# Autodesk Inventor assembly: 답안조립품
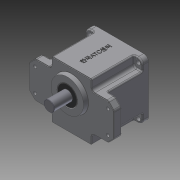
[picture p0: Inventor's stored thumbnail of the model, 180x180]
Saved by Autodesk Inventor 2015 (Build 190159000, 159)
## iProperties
Created: 2016-02
Part Number: 답안조립품
Document SubType Name: Assembly
Designer: Administrator
Author: Administrator
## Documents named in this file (10)
- C:\Users\Administrator\Desktop\460209V1019\답안조립품.iam
- C:\Users\Administrator\Desktop\460209V1019\본체.ipt
- C:\Users\Administrator\Desktop\460209V1019\커버.ipt
- C:\Users\Administrator\Desktop\460209V1019\볼트 M4 x 10.ipt
- C:\Users\Administrator\Desktop\460209V1019\오일실 8 22 7.ipt
- C:\Users\Administrator\Desktop\460209V1019\베어링 608.ipt
- C:\Users\Administrator\Desktop\460209V1019\메인축.ipt
- C:\Users\Administrator\Desktop\460209V1019\오일실 17 32 8.ipt
- C:\Users\Administrator\Desktop\460209V1019\베어링 6003.ipt
- C:\Users\Administrator\Desktop\460209V1019\서브축.ipt
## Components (2 placed, 1 different names)
1. ISO 4762 M4 x 10:1 — Insert:1
2. ISO 4762 M4 x 10:2 — Insert:2
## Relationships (2: Insert 2)
- Insert:1: ISO 4762 M4 x 10:1
- Insert:2: ISO 4762 M4 x 10:2
